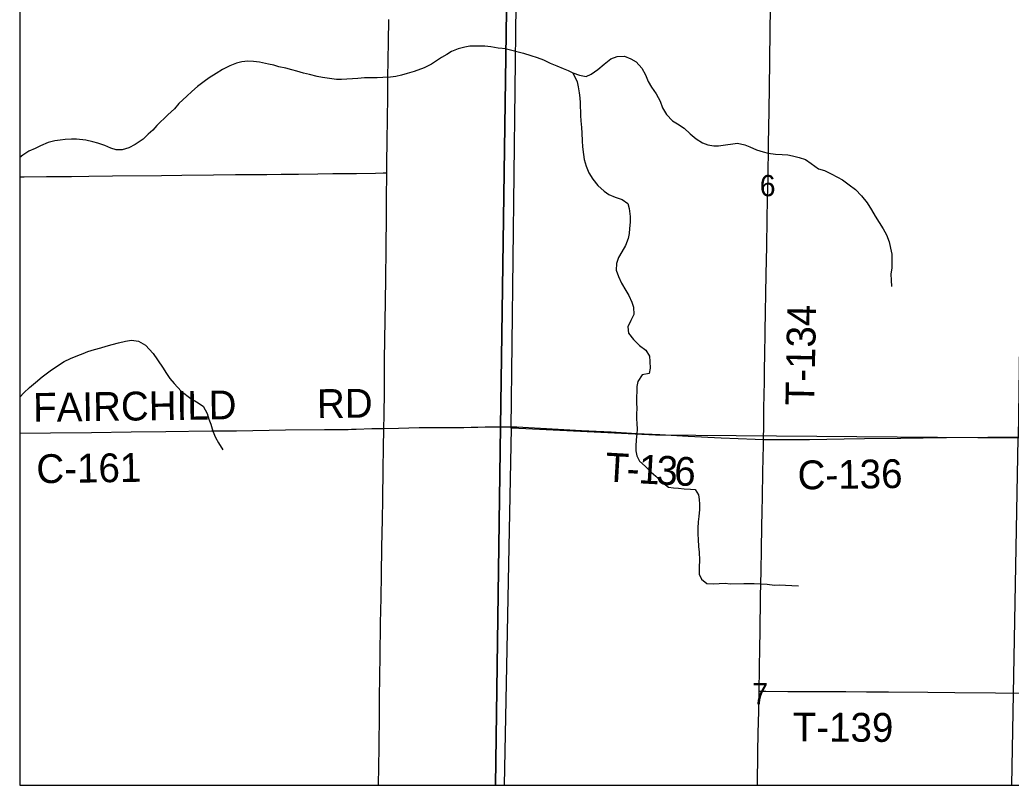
# Model space of a CAD drawing. Extents: x 0 to 34, y 0 to 22.
# Drawn here: x 2 to 3.955, y 14 to 15.508 of the extents above; entities that cross this region are included whole.
import ezdxf

# ---------------------------------------------------------------- set-up
doc = ezdxf.new("R2010")
doc.units = 0
for name, color, linetype in [('Default', 7, 'Continuous'), ('GM_X_City_Street', 7, 'Continuous'), ('GM_X_County_Road', 7, 'Continuous'), ('GM_X_County_Road_Text', 7, 'Continuous'), ('GM_X_Interchange_Ramps', 7, 'Continuous'), ('GM_X_Major_River_Text', 7, 'Continuous'), ('GM_X_Minor_River_Text', 7, 'Continuous'), ('GM_X_Section', 7, 'Continuous'), ('GM_X_Unincorporated_Location', 7, 'Continuous'), ('SH_Cut_Line', 7, 'Continuous'), ('SH_Text', 7, 'Continuous')]:
    doc.layers.add(name, color=color, linetype=linetype)

msp = doc.modelspace()

# ---------------------------------------------------------------- linework, layer by layer
at = {"layer": 'Default'}
for points in [[(2, 15.7064), (2, 14), (2.9377, 14), (2.9479, 14.7065), (2.9623, 15.7101), (2.8761, 15.7117), (2.786, 15.7133), (2.7519, 15.714), (2.73, 15.7143), (2.7239, 15.7144), (2.6587, 15.7141), (2.6058, 15.714), (2.5592, 15.7135), (2.5033, 15.7129), (2.4381, 15.7123), (2.407, 15.7118), (2.3635, 15.7113), (2.3293, 15.7107), (2.2206, 15.7088), (2.0933, 15.7073), (2.0405, 15.7068)], [(2.9554, 14), (3.9561, 14), (3.9687, 14.6839), (3.2537, 14.69), (2.9712, 14.7039), (2.9687, 14.7038)]]:
    msp.add_lwpolyline(points, close=True, dxfattribs=at)
msp.add_lwpolyline([(3.9843, 15.695), (3.9466, 15.6957), (3.9031, 15.6964), (3.8565, 15.6969), (3.8099, 15.6974), (3.6949, 15.6992), (3.639, 15.7003), (3.6049, 15.701), (3.5614, 15.7014), (3.5086, 15.702), (3.4828, 15.7023), (3.4402, 15.7026), (3.3377, 15.7042), (3.257, 15.7053), (3.2324, 15.706), (3.216, 15.7061), (3.1473, 15.7074), (3.0317, 15.7091), (2.988, 15.7097), (2.9623, 15.7101), (2.9479, 14.7065), (2.9377, 14), (7.9275, 14)], dxfattribs=at)
at = {"layer": 'GM_X_City_Street'}
for points in [[(2, 14.6935), (2.0607, 14.6941), (2.1415, 14.6951), (2.2193, 14.6961), (2.2877, 14.6972), (2.3779, 14.6981), (2.4272, 14.6983), (2.524, 14.7001), (2.601, 14.7008), (2.6277, 14.7011), (2.6477, 14.7012), (2.6541, 14.7014), (2.663, 14.7017), (2.6943, 14.7031), (2.7178, 14.7029)], [(2.7178, 14.7029), (2.7466, 14.7036), (2.7873, 14.7046), (2.7959, 14.7047), (2.8087, 14.7048), (2.8753, 14.7049), (2.89, 14.7054), (2.9031, 14.7057), (2.9175, 14.706), (2.9351, 14.7061), (2.9481, 14.706)], [(3.4667, 14.6814), (3.5073, 14.6811), (3.5571, 14.6814), (3.6255, 14.6826), (3.666, 14.6832), (3.7375, 14.6841), (3.7811, 14.6847), (3.8277, 14.685), (3.9086, 14.6859), (3.9646, 14.6861), (4.0113, 14.6858), (4.1015, 14.6844), (4.1637, 14.6833), (4.2209, 14.6828)], [(3.4578, 14.1854), (3.4578, 14.186), (3.4585, 14.2295), (3.4591, 14.2729), (3.4597, 14.3009), (3.4608, 14.3723), (3.4616, 14.4219), (3.4624, 14.4654), (3.4635, 14.5089), (3.464, 14.5399), (3.4645, 14.5678), (3.4654, 14.6175), (3.4666, 14.6703), (3.4667, 14.6814)], [(3.4544, 14), (3.4555, 14.0649), (3.4563, 14.1022), (3.4572, 14.1456), (3.4578, 14.1854)]]:
    msp.add_lwpolyline(points, dxfattribs=at)
at = {"layer": 'GM_X_County_Road'}
msp.add_lwpolyline([(2.7074, 14), (2.7083, 14.0738), (2.7092, 14.1421), (2.7093, 14.1639), (2.7101, 14.2229), (2.7104, 14.2466), (2.7106, 14.2605), (2.7109, 14.2788), (2.7111, 14.2944), (2.7113, 14.3192), (2.7124, 14.3689), (2.713, 14.4155), (2.7141, 14.4683), (2.7153, 14.5242), (2.7158, 14.5624), (2.7167, 14.6236), (2.7172, 14.664), (2.7178, 14.7029), (2.7182, 14.7292), (2.719, 14.7758), (2.7192, 14.8162), (2.7194, 14.838), (2.72, 14.8784), (2.721, 14.9529), (2.7216, 14.9995), (2.7224, 15.0554), (2.7224, 15.0648), (2.7229, 15.1157), (2.723, 15.1259), (2.7233, 15.1453), (2.7233, 15.164), (2.7237, 15.1981), (2.7237, 15.2067), (2.7239, 15.2261), (2.7244, 15.2696), (2.7255, 15.3566), (2.7258, 15.3939), (2.7269, 15.4653), (2.7278, 15.5088)], dxfattribs=at)
at = {"layer": 'GM_X_Interchange_Ramps'}
for points in [[(3.4667, 14.6814), (3.467, 14.7085), (3.4673, 14.7427), (3.4682, 14.7954), (3.4685, 14.8233), (3.469, 14.845), (3.47, 14.8947), (3.4719, 15.0063), (3.473, 15.0622), (3.4738, 15.1149), (3.4746, 15.1553), (3.4754, 15.1956), (3.4765, 15.2639), (3.4774, 15.329), (3.4789, 15.4252), (3.4799, 15.4903), (3.4816, 15.602), (3.4826, 15.6703), (3.4829, 15.6946), (3.483, 15.7017)], [(2, 15.1988), (2.0088, 15.1989), (2.0523, 15.1996), (2.102, 15.1999), (2.1362, 15.2003), (2.1828, 15.2007), (2.2792, 15.2017), (2.3196, 15.2023), (2.3817, 15.2032), (2.4252, 15.2034), (2.4594, 15.2037), (2.4874, 15.2037), (2.5153, 15.204), (2.5493, 15.2044), (2.5876, 15.2049), (2.6171, 15.2052), (2.6393, 15.2055), (2.6638, 15.2055), (2.7011, 15.2062), (2.7166, 15.2066), (2.7237, 15.2067)], [(2.9481, 14.706), (2.9802, 14.7059), (3.0267, 14.7038), (3.1073, 14.6992), (3.1662, 14.6961), (3.2158, 14.6933), (3.2623, 14.6909), (3.3181, 14.6878), (3.3833, 14.6846), (3.4501, 14.6817), (3.4667, 14.6814)], [(3.4667, 14.6814), (3.5073, 14.6811), (3.5571, 14.6814), (3.6255, 14.6826), (3.666, 14.6832), (3.7375, 14.6841), (3.7811, 14.6847), (3.8277, 14.685), (3.9086, 14.6859), (3.9646, 14.6861), (4.0113, 14.6858), (4.1015, 14.6844), (4.1637, 14.6833), (4.2209, 14.6828)], [(3.4578, 14.1854), (3.4578, 14.186), (3.4585, 14.2295), (3.4591, 14.2729), (3.4597, 14.3009), (3.4608, 14.3723), (3.4616, 14.4219), (3.4624, 14.4654), (3.4635, 14.5089), (3.464, 14.5399), (3.4645, 14.5678), (3.4654, 14.6175), (3.4666, 14.6703), (3.4667, 14.6814)], [(3.4544, 14), (3.4555, 14.0649), (3.4563, 14.1022), (3.4572, 14.1456), (3.4578, 14.1854)], [(3.4578, 14.1854), (3.4678, 14.1852), (3.4709, 14.1852), (3.5143, 14.1847), (3.5485, 14.1847), (3.6292, 14.1844), (3.6696, 14.1841), (3.7131, 14.1838), (3.7907, 14.1831), (3.8435, 14.1828), (3.9243, 14.1819), (3.9801, 14.1813), (4.0702, 14.18), (4.1199, 14.1792), (4.2147, 14.1777)]]:
    msp.add_lwpolyline(points, dxfattribs=at)
at = {"layer": 'GM_X_Section'}
for points in [[(2.9597, 15.4514), (2.9431, 15.4526), (2.9291, 15.4554), (2.9173, 15.4563), (2.9052, 15.4565), (2.8877, 15.4564), (2.8775, 15.4546), (2.8645, 15.451), (2.8515, 15.4458), (2.842, 15.4403), (2.8313, 15.434), (2.8217, 15.4273), (2.8117, 15.4213), (2.7976, 15.4139), (2.7778, 15.4066), (2.7637, 15.4023), (2.7526, 15.3994), (2.7412, 15.3965), (2.7309, 15.3951), (2.7161, 15.3945), (2.7044, 15.3939), (2.6922, 15.3941), (2.6797, 15.3939), (2.6664, 15.3929), (2.6558, 15.3919), (2.6451, 15.3917), (2.6341, 15.3911), (2.6243, 15.3908), (2.611, 15.3925), (2.5966, 15.395), (2.5864, 15.397), (2.5713, 15.4007), (2.5592, 15.4035), (2.5463, 15.4071), (2.5361, 15.4095), (2.5244, 15.4131), (2.5108, 15.4159), (2.501, 15.4187), (2.4904, 15.4211), (2.4726, 15.4248), (2.4608, 15.4264), (2.4495, 15.427), (2.4377, 15.4256), (2.427, 15.4227), (2.414, 15.4176), (2.3999, 15.4106), (2.3873, 15.4028), (2.3735, 15.3942), (2.3636, 15.3871), (2.3501, 15.3767), (2.3394, 15.3674), (2.3294, 15.358), (2.3133, 15.3438), (2.3048, 15.3329), (2.2917, 15.3213), (2.2702, 15.3004), (2.2625, 15.2906), (2.2529, 15.2832), (2.2429, 15.2731), (2.2272, 15.2626), (2.2149, 15.256), (2.202, 15.2524), (2.1898, 15.2521), (2.1793, 15.2553), (2.1676, 15.2604), (2.154, 15.2655), (2.1441, 15.2679), (2.1302, 15.2712), (2.112, 15.2733), (2.1021, 15.2734), (2.0896, 15.2728), (2.0793, 15.2711), (2.069, 15.2697), (2.0557, 15.2668), (2.0405, 15.2598), (2.0301, 15.2551), (2.0175, 15.2492), (2.0057, 15.2417), (2, 15.2368)], [(2.9597, 15.4514), (2.993, 15.4429), (3.0078, 15.4384), (3.0199, 15.4339), (3.0325, 15.4294), (3.0458, 15.423), (3.0587, 15.4177), (3.0712, 15.4124), (3.0811, 15.4083), (3.0906, 15.4042), (3.1035, 15.3993), (3.1168, 15.3967), (3.1266, 15.4012), (3.1399, 15.4104), (3.1524, 15.4207), (3.1652, 15.4317), (3.1781, 15.4363), (3.1921, 15.4367), (3.2051, 15.4315), (3.2153, 15.4254), (3.2264, 15.4133), (3.234, 15.3997), (3.2394, 15.3868), (3.2455, 15.3755), (3.2546, 15.3626), (3.2626, 15.3478), (3.2672, 15.335), (3.2753, 15.3217), (3.2871, 15.3096), (3.2969, 15.3032), (3.3099, 15.2949), (3.3217, 15.2839), (3.3338, 15.2737), (3.346, 15.2662), (3.3566, 15.2621), (3.3684, 15.2602), (3.3779, 15.2602), (3.3915, 15.2618), (3.4059, 15.2641), (3.4154, 15.2653), (3.4295, 15.2623), (3.4397, 15.2578), (3.4526, 15.2521), (3.4656, 15.2484), (3.4758, 15.2458), (3.4899, 15.2439), (3.5031, 15.2432), (3.5145, 15.2421), (3.524, 15.2406), (3.5369, 15.2373), (3.5491, 15.2328), (3.5605, 15.2252), (3.5753, 15.215), (3.5871, 15.2116), (3.6, 15.2049), (3.6125, 15.1985), (3.622, 15.1932), (3.6354, 15.183), (3.6479, 15.1743), (3.6597, 15.1614), (3.6708, 15.1474), (3.6795, 15.1338), (3.6868, 15.1213), (3.6944, 15.1088), (3.7024, 15.0967), (3.7089, 15.0846), (3.7143, 15.071), (3.717, 15.0581), (3.7193, 15.0464), (3.7197, 15.0327), (3.7194, 15.0198), (3.7179, 15.0073), (3.718, 14.9955), (3.7191, 14.983)], [(3.0906, 15.4042), (3.099, 15.386), (3.1013, 15.3765), (3.1029, 15.3644), (3.1041, 15.3545), (3.1049, 15.3447), (3.1057, 15.3196), (3.1061, 15.3094), (3.1077, 15.2965), (3.1081, 15.2851), (3.1089, 15.27), (3.1093, 15.2582), (3.1113, 15.2427), (3.1128, 15.2328), (3.1167, 15.2199), (3.122, 15.207), (3.1297, 15.1942), (3.1396, 15.1821), (3.1521, 15.1704), (3.1616, 15.1643), (3.1742, 15.1587), (3.1875, 15.1542), (3.1989, 15.1466), (3.2019, 15.1368), (3.2035, 15.1208), (3.2036, 15.1098), (3.2025, 15.0973), (3.2014, 15.0875), (3.1999, 15.0772), (3.1942, 15.0635), (3.1871, 15.0514), (3.1807, 15.04), (3.1769, 15.0282), (3.1762, 15.0149), (3.1804, 15.0024), (3.1862, 14.9896), (3.1949, 14.9752), (3.2007, 14.9653), (3.2072, 14.9521), (3.2102, 14.9422), (3.2107, 14.9274), (3.2046, 14.916), (3.199, 14.9031), (3.2006, 14.8906), (3.2101, 14.8785), (3.2223, 14.8668), (3.2348, 14.8574), (3.2417, 14.8456), (3.2425, 14.835), (3.2433, 14.8217), (3.241, 14.8115), (3.227, 14.8088), (3.2187, 14.7955), (3.2169, 14.786), (3.2165, 14.7754), (3.2162, 14.7659), (3.2162, 14.7534), (3.2166, 14.7424), (3.2163, 14.7321), (3.2159, 14.7223), (3.2167, 14.7128), (3.2172, 14.7018), (3.2168, 14.6923), (3.2157, 14.6806), (3.215, 14.6684), (3.2147, 14.6586), (3.2166, 14.6491), (3.2223, 14.6385), (3.2333, 14.6287), (3.2448, 14.6169), (3.2543, 14.609), (3.2665, 14.5969), (3.2794, 14.5875), (3.2889, 14.586), (3.2987, 14.5853), (3.3101, 14.5838), (3.3223, 14.5835), (3.3318, 14.5827), (3.3382, 14.5725), (3.3398, 14.563), (3.3402, 14.5536), (3.3402, 14.5433), (3.3392, 14.5297), (3.338, 14.519), (3.337, 14.5065), (3.337, 14.4944), (3.3374, 14.4841), (3.3382, 14.4701), (3.3394, 14.4591), (3.3406, 14.4432), (3.3395, 14.4295), (3.3396, 14.4159), (3.3441, 14.406), (3.3548, 14.3977), (3.3688, 14.397), (3.3791, 14.3974), (3.3912, 14.3979), (3.4011, 14.3971), (3.428, 14.3972), (3.4382, 14.3976), (3.4481, 14.3973)], [(2, 14.7645), (2.0081, 14.7732), (2.0192, 14.784), (2.0307, 14.7937), (2.0441, 14.8045), (2.0599, 14.8165), (2.0725, 14.825), (2.0874, 14.8347), (2.1, 14.841), (2.1145, 14.8468), (2.1248, 14.8509), (2.1344, 14.8545), (2.1473, 14.8589), (2.1595, 14.8622), (2.1702, 14.8651), (2.1824, 14.8687), (2.1946, 14.8719), (2.2083, 14.8752), (2.22, 14.8769), (2.2341, 14.8748), (2.2476, 14.8674), (2.2629, 14.8505), (2.2812, 14.8237), (2.289, 14.8115), (2.296, 14.8015), (2.3043, 14.7919), (2.3181, 14.7762), (2.3369, 14.7619), (2.3485, 14.7553), (2.3617, 14.7468), (2.3695, 14.7326), (2.3727, 14.7216), (2.3764, 14.7117), (2.3808, 14.698), (2.3859, 14.6854), (2.3918, 14.675), (2.4, 14.6609)], [(3.4481, 14.3973), (3.4614, 14.397), (3.4739, 14.3959), (3.4883, 14.3944), (3.4986, 14.3948), (3.5096, 14.3941), (3.5225, 14.3938), (3.5357, 14.393)]]:
    msp.add_lwpolyline(points, dxfattribs=at)
at = {"layer": 'GM_X_Unincorporated_Location'}
msp.add_lwpolyline([(3.983, 15.6924), (3.9687, 14.6839), (3.2537, 14.69), (2.9712, 14.7039), (2.9687, 14.7038), (2.9805, 15.7055)], close=True, dxfattribs=at)
at = {"layer": 'SH_Cut_Line'}
for p, q in [((2, 21), (2, 14)), ((2, 14), (9, 14))]:
    msp.add_line(p, q, dxfattribs=at)
at = {"layer": 'SH_Text'}
for points in [[(2.9842, 20.8), (2, 20.8), (2, 14), (2.9377, 14), (2.9479, 14.7065), (2.9623, 15.7101), (2.9708, 17.6769), (2.9753, 18.7199), (2.9796, 19.7242), (2.9904, 20.3395), (2.984, 20.7397)], [(2.9377, 14), (8.8, 14), (8.8, 20.8), (2.9842, 20.8), (2.984, 20.7397), (2.9904, 20.3395), (2.9796, 19.7242), (2.9753, 18.7199), (2.9708, 17.6769), (2.9623, 15.7101), (2.9479, 14.7065)]]:
    msp.add_lwpolyline(points, close=True, dxfattribs=at)

# ---------------------------------------------------------------- texts
at = {"layer": 'GM_X_County_Road_Text'}
for s, height, rotation, p in [('T-134', 0.05682, 88.8896, (3.5665, 14.7481)), ('T', 0.0568, 356.7069, (3.153, 14.5989)), ('1', 0.0568, 356.7391, (3.2188, 14.5951)), ('3', 0.0568, 356.8625, (3.2539, 14.5931)), ('6', 0.0568, 357.4476, (3.2895, 14.5911)), ('-', 0.0568, 356.7041, (3.1955, 14.5964)), ('T-139', 0.05682, 359.7214, (3.524, 14.0862))]:
    msp.add_text(s, height=height, rotation=rotation, dxfattribs=at).set_placement(p)
at = {"layer": 'GM_X_Major_River_Text'}
for s, p in [('6', (3.4591, 15.1607)), ('7', (3.4445, 14.1596))]:
    msp.add_text(s, height=0.0419, rotation=0, dxfattribs=at).set_placement(p)
at = {"layer": 'GM_X_Minor_River_Text'}
for s, rotation, p in [('RD', 0.4787, (2.5862, 14.7235)), ('FAIRCHILD', 0.769, (2.0266, 14.716)), ('C-161', 0.8232, (2.033, 14.595)), ('C-136', 0.823, (3.5341, 14.5828))]:
    msp.add_text(s, height=0.05682, rotation=rotation, dxfattribs=at).set_placement(p)

doc.saveas('drawing.dxf')
